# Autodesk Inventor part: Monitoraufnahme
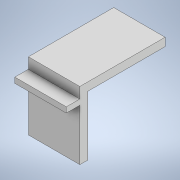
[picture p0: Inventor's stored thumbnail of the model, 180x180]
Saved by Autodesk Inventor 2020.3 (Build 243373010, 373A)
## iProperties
Created: 2020-07
Part Number: Monitoraufnahme
Material: Generisch
Document SubType Name: Modeling
Designer: Ruben
Density: 1 g/cm^3
Appearance: Vorgabe
Author: Ruben
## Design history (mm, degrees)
sketch "Skizze1"
  geometry: L1 (-17.5, -25)-(17.5, -25); L2 (17.5, -25)-(17.5, 25); L3 (17.5, 25)-(-17.5, 25); L4 (-17.5, 25)-(-17.5, -25); L5 (-17.5, -25)-(17.5, 25); L6 (17.5, -25)-(-17.5, 25); 1 further point
  constraints: 12 end point, 2 midpoint, 2 parallel, 1 horizontal, 1 perpendicular
  dimensions: "d0" = 35 distance of L3.end L2.end; "d1" = 50 distance of L2.end L1.end
extrude "Links_Monitor" new body sketch "Skizze1" distance "d2" = 3; taper "d3" = 0 deg
sketch "Skizze2"
  geometry: L1 (35, 0)-(0, 0) reference; L2 (35, 0)-(0, 0); L3 (0, 0)-(0, 60); L4 (0, 60)-(35, 60); L5 (35, 60)-(35, 0); 2 further points
  constraints: 8 end point, 2 parallel, 1 horizontal, 1 perpendicular
  dimensions: "d4" = 35 distance of L3.end L4.end; "d5" = 60 distance of L2.end L3.end
extrude "Oberseite_Monitor" join sketch "Skizze2" distance "d6" = 3; taper "d7" = 0 deg
sketch "Skizze4"
  geometry: L1 (0, 0)-(0, 50) reference; L2 (0, 50)-(63, 50); L3 (63, 50)-(63, 44); L4 (6, 0)-(0, 0); L5 (0, 0)-(0, 50); L6 (6, 0)-(6, 44); L7 (6, 44)-(63, 44); L8 (63, 47)-(3, 47) reference; L9 (3, 0)-(3, 47) reference; 1 further point
  constraints: 12 end point, 2 parallel, 2 perpendicular, 1 horizontal, 1 vertical
  dimensions: "d11" = 3 distance between parallel lines of L8 L7; "d12" = 3 distance between parallel lines of L9 L6; "d13" = 63 distance between parallel lines of L1 L3
extrude "Lippe_Monitor" join sketch "Skizze4" distance "d14" = 3; taper "d15" = 0 deg
sketch "Skizze5"
  geometry: L1 (20.5, -25)-(20.5, 19) reference; L2 (20.5, 17)-(-17.5, 17); L3 (-17.5, 25)-(-17.5, -25) reference; L4 (-17.5, 13)-(20.5, 13); 1 further point
  constraints: 4 end point, 4 point on line, 1 horizontal, 1 perpendicular
  dimensions: "d16" = 4 distance between parallel lines of L2 L4; "d17" = 13 distance from line of point (0, 0) L4
extrude "Montage" join sketch "Skizze5" distance "d18" = 10; taper "d19" = 0 deg
node "Volumenkörper1"
